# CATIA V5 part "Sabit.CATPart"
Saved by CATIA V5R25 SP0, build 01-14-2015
Part number: giris
Bounding box of the stored display mesh (mm): x 0 to 10, y -12.486 to 287.486, z -12.5 to 12.5
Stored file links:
  C:\Users\Aidata\Downloads\Sabit.CATPart
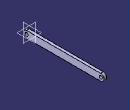
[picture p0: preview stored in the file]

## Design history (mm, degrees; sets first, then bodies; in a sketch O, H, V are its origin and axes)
Body1 (main body)
  Sketch1 on yz-plane, origin (0, 0, 0), H (0, 1, 0), V (0, 0, 1)
    construction line L1 (0, 0) -> (275, 0)
    line L2 (0, 12.5) -> (275, 12.5)
    line L3 (275, -12.5) -> (0, -12.5)
    arc A1 centre (275, 0) radius 12.5 from (275, 12.5) to (275, -12.5) cw
    arc A2 centre (0, 0) radius 12.5 from (0, -12.5) to (0, 12.5) cw
    circle A3 centre (0, 0) radius 6
    circle A4 centre (275, 0) radius 6
    distance L3 L2 = 25
    radius A3 = 6
    radius A4 = 6
    distance A1 A2 = 300
    horizontal: L1 H
    tangency: A1 L2, A2 L2, A1 L3, A2 L3
  Pad1: profile Sketch1, direction (1, 0, 0), length 10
